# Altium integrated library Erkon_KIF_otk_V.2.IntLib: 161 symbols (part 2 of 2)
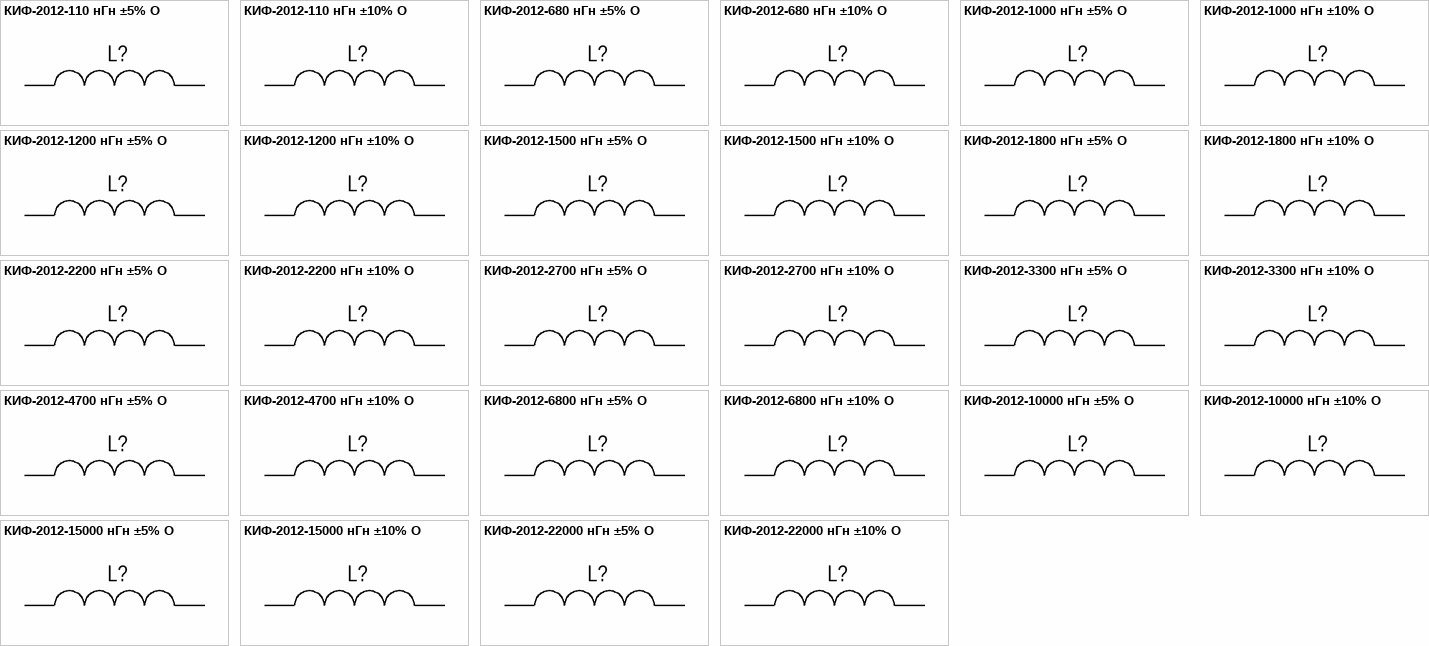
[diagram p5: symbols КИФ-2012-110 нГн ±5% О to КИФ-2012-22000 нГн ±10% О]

## КИФ-2012-1800 нГн ±5% О
designator L?, comment 1800 нГн ±5%  (value not drawn)
Катушка индуктивности с ферритовым сердечником; Добротность, не менее: 13; Резонансная частота, не менее: 0,3 ГГц; Сопротивление обмотки постоянноми току, не более: 1.2 Ом; Допустимый ток обмотки: 370 мА; Диапазон рабочих температур: от -60 до +125 ℃; Упаковка: Катушка и лента; Типоразмер: 2012 (0805); Технология монтажа: SMT; Изготовитель: АО "НПО "ЭРКОН"
footprint КИФ-2012-O (Катушка индуктивности с ферритовым сердечником типоразмер 2012(0805))
pins: 1, 2

## КИФ-2012-1800 нГн ±10% О
designator L?, comment 1800 нГн ±10%  (value not drawn)
Катушка индуктивности с ферритовым сердечником; Добротность, не менее: 13; Резонансная частота, не менее: 0.3 ГГц; Сопротивление обмотки постоянноми току, не более: 1.2 Ом; Допустимый ток обмотки: 370 мА; Диапазон рабочих температур: от -60 до +125 ℃; Упаковка: Катушка и лента; Типоразмер: 2012 (0805); Технология монтажа: SMT; Изготовитель: АО "НПО "ЭРКОН"
footprint КИФ-2012-O (Катушка индуктивности с ферритовым сердечником типоразмер 2012(0805))
pins: 1, 2

## КИФ-2012-2200 нГн ±5% О
designator L?, comment 2200 нГн ±5%  (value not drawn)
Катушка индуктивности с ферритовым сердечником; Добротность, не менее: 13; Резонансная частота, не менее: 0.105 ГГц; Сопротивление обмотки постоянноми току, не более: 1.47 Ом; Допустимый ток обмотки: 350 мА; Диапазон рабочих температур: от -60 до +125 ℃; Упаковка: Катушка и лента; Типоразмер: 2012 (0805); Технология монтажа: SMT; Изготовитель: АО "НПО "ЭРКОН"
footprint КИФ-2012-O (Катушка индуктивности с ферритовым сердечником типоразмер 2012(0805))
pins: 1, 2

## КИФ-2012-2200 нГн ±10% О
designator L?, comment 2200 нГн ±10%  (value not drawn)
Катушка индуктивности с ферритовым сердечником; Добротность, не менее: 13; Резонансная частота, не менее: 0.105 ГГц; Сопротивление обмотки постоянноми току, не более: 1.47 Ом; Допустимый ток обмотки: 350 мА; Диапазон рабочих температур: от -60 до +125 ℃; Упаковка: Катушка и лента; Типоразмер: 2012 (0805); Технология монтажа: SMT; Изготовитель: АО "НПО "ЭРКОН"
footprint КИФ-2012-O (Катушка индуктивности с ферритовым сердечником типоразмер 2012(0805))
pins: 1, 2

## КИФ-2012-2700 нГн ±5% О
designator L?, comment 2700 нГн ±5%  (value not drawn)
Катушка индуктивности с ферритовым сердечником; Добротность, не менее: 13; Резонансная частота, не менее: 0.10 ГГц; Сопротивление обмотки постоянноми току, не более: 1.7 Ом; Допустимый ток обмотки: 320 мА; Диапазон рабочих температур: от -60 до +125 ℃; Упаковка: Катушка и лента; Типоразмер: 2012 (0805); Технология монтажа: SMT; Изготовитель: АО "НПО "ЭРКОН"
footprint КИФ-2012-O (Катушка индуктивности с ферритовым сердечником типоразмер 2012(0805))
pins: 1, 2

## КИФ-2012-2700 нГн ±10% О
designator L?, comment 2700 нГн ±10%  (value not drawn)
Катушка индуктивности с ферритовым сердечником; Добротность, не менее: 13; Резонансная частота, не менее: 0.10 ГГц; Сопротивление обмотки постоянноми току, не более: 1.7 Ом; Допустимый ток обмотки: 320 мА; Диапазон рабочих температур: от -60 до +125 ℃; Упаковка: Катушка и лента; Типоразмер: 2012 (0805); Технология монтажа: SMT; Изготовитель: АО "НПО "ЭРКОН"
footprint КИФ-2012-O (Катушка индуктивности с ферритовым сердечником типоразмер 2012(0805))
pins: 1, 2

## КИФ-2012-3300 нГн ±5% О
designator L?, comment 3300 нГн ±5%  (value not drawn)
Катушка индуктивности с ферритовым сердечником; Добротность, не менее: 13; Резонансная частота, не менее: 0.085 ГГц; Сопротивление обмотки постоянноми току, не более: 1.8 Ом; Допустимый ток обмотки: 330 мА; Диапазон рабочих температур: от -60 до +125 ℃; Упаковка: Катушка и лента; Типоразмер: 2012 (0805); Технология монтажа: SMT; Изготовитель: АО "НПО "ЭРКОН"
footprint КИФ-2012-O (Катушка индуктивности с ферритовым сердечником типоразмер 2012(0805))
pins: 1, 2

## КИФ-2012-3300 нГн ±10% О
designator L?, comment 3300 нГн ±10%  (value not drawn)
Катушка индуктивности с ферритовым сердечником; Добротность, не менее: 13; Резонансная частота, не менее: 0.085 ГГц; Сопротивление обмотки постоянноми току, не более: 1.8 Ом; Допустимый ток обмотки: 330 мА; Диапазон рабочих температур: от -60 до +125 ℃; Упаковка: Катушка и лента; Типоразмер: 2012 (0805); Технология монтажа: SMT; Изготовитель: АО "НПО "ЭРКОН"
footprint КИФ-2012-O (Катушка индуктивности с ферритовым сердечником типоразмер 2012(0805))
pins: 1, 2

## КИФ-2012-4700 нГн ±5% О
designator L?, comment 4700 нГн ±5%  (value not drawn)
Катушка индуктивности с ферритовым сердечником; Добротность, не менее: 13; Резонансная частота, не менее: 0.055 ГГц; Сопротивление обмотки постоянноми току, не более: 2.2 Ом; Допустимый ток обмотки: 280 мА; Диапазон рабочих температур: от -60 до +125 ℃; Упаковка: Катушка и лента; Типоразмер: 2012 (0805); Технология монтажа: SMT; Изготовитель: АО "НПО "ЭРКОН"
footprint КИФ-2012-O (Катушка индуктивности с ферритовым сердечником типоразмер 2012(0805))
pins: 1, 2

## КИФ-2012-4700 нГн ±10% О
designator L?, comment 4700 нГн ±10%  (value not drawn)
Катушка индуктивности с ферритовым сердечником; Добротность, не менее: 13; Резонансная частота, не менее: 0.055 ГГц; Сопротивление обмотки постоянноми току, не более: 2.2 Ом; Допустимый ток обмотки: 280 мА; Диапазон рабочих температур: от -60 до +125 ℃; Упаковка: Катушка и лента; Типоразмер: 2012 (0805); Технология монтажа: SMT; Изготовитель: АО "НПО "ЭРКОН"
footprint КИФ-2012-O (Катушка индуктивности с ферритовым сердечником типоразмер 2012(0805))
pins: 1, 2

## КИФ-2012-6800 нГн ±5% О
designator L?, comment 6800 нГн ±5%  (value not drawn)
Катушка индуктивности с ферритовым сердечником; Добротность, не менее: 13; Резонансная частота, не менее: 0.035 ГГц; Сопротивление обмотки постоянноми току, не более: 2.8 Ом; Допустимый ток обмотки: 240 мА; Диапазон рабочих температур: от -60 до +125 ℃; Упаковка: Катушка и лента; Типоразмер: 2012 (0805); Технология монтажа: SMT; Изготовитель: АО "НПО "ЭРКОН"
footprint КИФ-2012-O (Катушка индуктивности с ферритовым сердечником типоразмер 2012(0805))
pins: 1, 2

## КИФ-2012-6800 нГн ±10% О
designator L?, comment 6800 нГн ±10%  (value not drawn)
Катушка индуктивности с ферритовым сердечником; Добротность, не менее: 13; Резонансная частота, не менее: 0.035 ГГц; Сопротивление обмотки постоянноми току, не более: 2.8 Ом; Допустимый ток обмотки: 240 мА; Диапазон рабочих температур: от -60 до +125 ℃; Упаковка: Катушка и лента; Типоразмер: 2012 (0805); Технология монтажа: SMT; Изготовитель: АО "НПО "ЭРКОН"
footprint КИФ-2012-O (Катушка индуктивности с ферритовым сердечником типоразмер 2012(0805))
pins: 1, 2

## КИФ-2012-10000 нГн ±5% О
designator L?, comment 10000 нГн ±5%  (value not drawn)
Катушка индуктивности с ферритовым сердечником; Добротность, не менее: 13; Резонансная частота, не менее: 0.019 ГГц; Сопротивление обмотки постоянноми току, не более: 3.3 Ом; Допустимый ток обмотки: 230 мА; Диапазон рабочих температур: от -60 до +125 ℃; Упаковка: Катушка и лента; Типоразмер: 2012 (0805); Технология монтажа: SMT; Изготовитель: АО "НПО "ЭРКОН"
footprint КИФ-2012-O (Катушка индуктивности с ферритовым сердечником типоразмер 2012(0805))
pins: 1, 2

## КИФ-2012-10000 нГн ±10% О
designator L?, comment 10000 нГн ±10%  (value not drawn)
Катушка индуктивности с ферритовым сердечником; Добротность, не менее: 13; Резонансная частота, не менее: 0.019 ГГц; Сопротивление обмотки постоянноми току, не более: 3.3 Ом; Допустимый ток обмотки: 230 мА; Диапазон рабочих температур: от -60 до +125 ℃; Упаковка: Катушка и лента; Типоразмер: 2012 (0805); Технология монтажа: SMT; Изготовитель: АО "НПО "ЭРКОН"
footprint КИФ-2012-O (Катушка индуктивности с ферритовым сердечником типоразмер 2012(0805))
pins: 1, 2

## КИФ-2012-15000 нГн ±5% О
designator L?, comment 15000 нГн ±5%  (value not drawn)
Катушка индуктивности с ферритовым сердечником; Добротность, не менее: 13; Резонансная частота, не менее: 0.015 ГГц; Сопротивление обмотки постоянноми току, не более: 6.3 Ом; Допустимый ток обмотки: 150 мА; Диапазон рабочих температур: от -60 до +125 ℃; Упаковка: Катушка и лента; Типоразмер: 2012 (0805); Технология монтажа: SMT; Изготовитель: АО "НПО "ЭРКОН"
footprint КИФ-2012-O (Катушка индуктивности с ферритовым сердечником типоразмер 2012(0805))
pins: 1, 2

## КИФ-2012-15000 нГн ±10% О
designator L?, comment 15000 нГн ±10%  (value not drawn)
Катушка индуктивности с ферритовым сердечником; Добротность, не менее: 13; Резонансная частота, не менее: 0.015 ГГц; Сопротивление обмотки постоянноми току, не более: 6.3 Ом; Допустимый ток обмотки: 150 мА; Диапазон рабочих температур: от -60 до +125 ℃; Упаковка: Катушка и лента; Типоразмер: 2012 (0805); Технология монтажа: SMT; Изготовитель: АО "НПО "ЭРКОН"
footprint КИФ-2012-O (Катушка индуктивности с ферритовым сердечником типоразмер 2012(0805))
pins: 1, 2

## КИФ-2012-22000 нГн ±5% О
designator L?, comment 22000 нГн ±5%  (value not drawn)
Катушка индуктивности с ферритовым сердечником; Добротность, не менее: 13; Резонансная частота, не менее: 0.01 ГГц; Сопротивление обмотки постоянноми току, не более: 10 Ом; Допустимый ток обмотки: 120 мА; Диапазон рабочих температур: от -60 до +125 ℃; Упаковка: Катушка и лента; Типоразмер: 2012 (0805); Технология монтажа: SMT; Изготовитель: АО "НПО "ЭРКОН"
footprint КИФ-2012-O (Катушка индуктивности с ферритовым сердечником типоразмер 2012(0805))
pins: 1, 2

## КИФ-2012-22000 нГн ±10% О
designator L?, comment 22000 нГн ±10%  (value not drawn)
Катушка индуктивности с ферритовым сердечником; Добротность, не менее: 13; Резонансная частота, не менее: 0.01 ГГц; Сопротивление обмотки постоянноми току, не более: 10 Ом; Допустимый ток обмотки: 120 мА; Диапазон рабочих температур: от -60 до +125 ℃; Упаковка: Катушка и лента; Типоразмер: 2012 (0805); Технология монтажа: SMT; Изготовитель: АО "НПО "ЭРКОН"
footprint КИФ-2012-O (Катушка индуктивности с ферритовым сердечником типоразмер 2012(0805))
pins: 1, 2


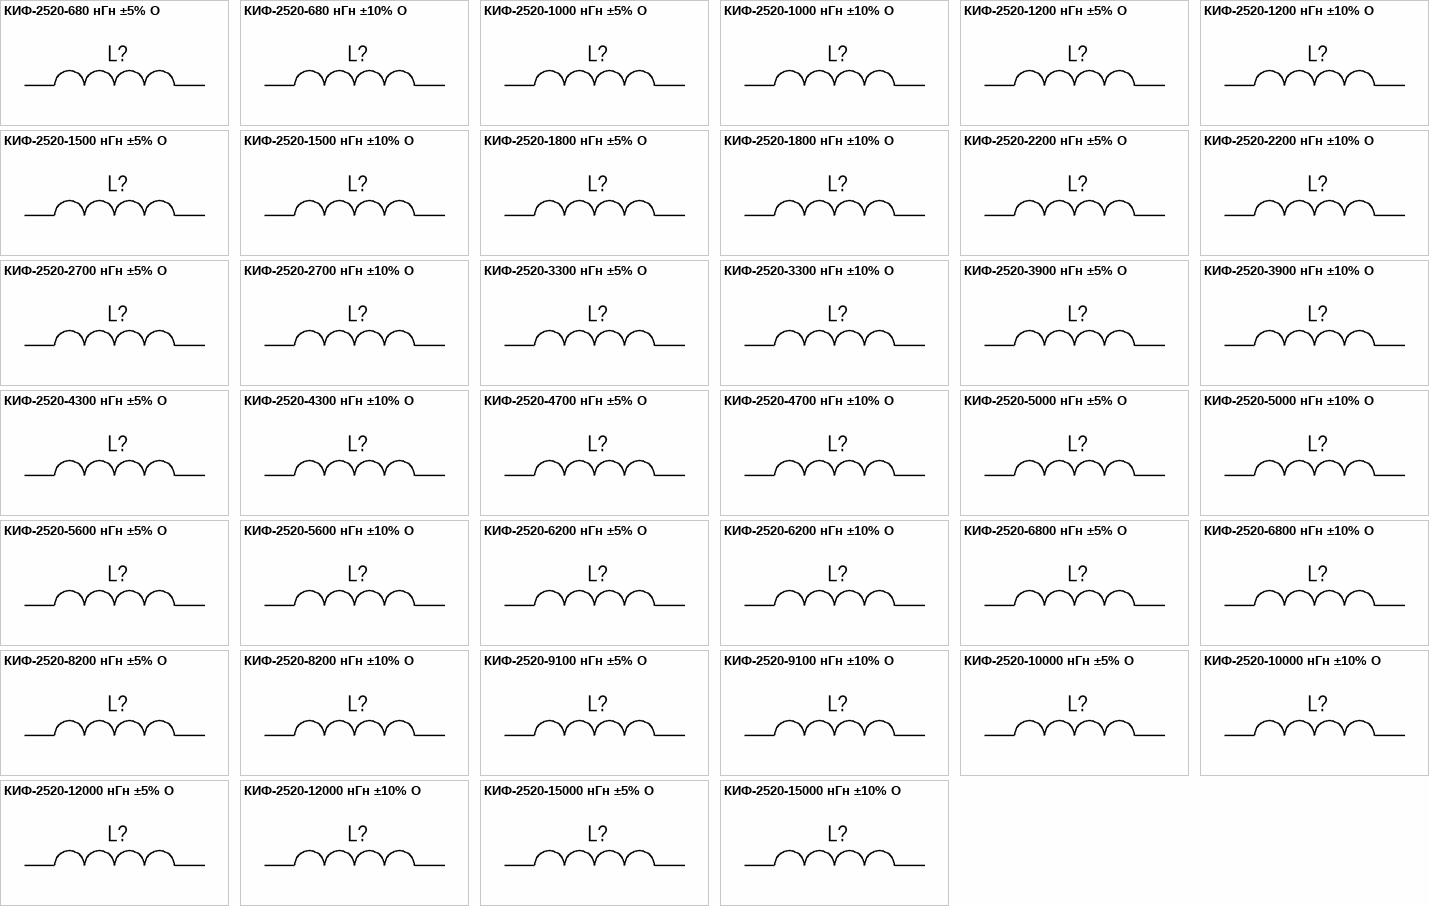
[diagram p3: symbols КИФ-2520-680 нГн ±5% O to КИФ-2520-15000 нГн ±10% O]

## КИФ-2520-680 нГн ±5% O
designator L?, comment 680 нГн ±5%  (value not drawn)
Катушка индуктивности с ферритовым сердечником; Номиналиная индуктивность: 680 нГн; Добротность, не менее: 50; Резонансная частота, не менее: 0.36 ГГц; Сопротивление обмотки постоянноми току, не более: 0.33 Ом; Допустимый ток обмотки: 600 мА; Упаковка: Катушка и лента; Типоразмер: 2520 (1008); Технология монтажа: SMT; Изготовитель: АО "НПО "ЭРКОН"
footprint КИФ-2520-O (Катушка индуктивности с ферритовым сердечником типоразмер 2520(1008))
pins: 1, 2

## КИФ-2520-680 нГн ±10% O
designator L?, comment 680 нГн ±10%  (value not drawn)
Катушка индуктивности с ферритовым сердечником; Номиналиная индуктивность: 680 нГн; Добротность, не менее: 50; Резонансная частота, не менее: 0.36 ГГц; Сопротивление обмотки постоянноми току, не более: 0.33 Ом; Допустимый ток обмотки: 600 мА; Упаковка: Катушка и лента; Типоразмер: 2520 (1008); Технология монтажа: SMT; Изготовитель: АО "НПО "ЭРКОН"
footprint КИФ-2520-O (Катушка индуктивности с ферритовым сердечником типоразмер 2520(1008))
pins: 1, 2

## КИФ-2520-1000 нГн ±5% O
designator L?, comment 1000 нГн ±5%  (value not drawn)
Катушка индуктивности с ферритовым сердечником; Добротность, не менее: 45; Резонансная частота, не менее: 0.33 ГГц; Сопротивление обмотки постоянноми току, не более: 0.4 Ом; Допустимый ток обмотки: 500 мА; Упаковка: Катушка и лента; Типоразмер: 2520 (1008); Технология монтажа: SMT; Изготовитель: АО "НПО "ЭРКОН"
footprint КИФ-2520-O (Катушка индуктивности с ферритовым сердечником типоразмер 2520(1008))
pins: 1, 2

## КИФ-2520-1000 нГн ±10% O
designator L?, comment 1000 нГн ±10%  (value not drawn)
Катушка индуктивности с ферритовым сердечником; Добротность, не менее: 45; Резонансная частота, не менее: 0.33 ГГц; Сопротивление обмотки постоянноми току, не более: 0.4 Ом; Допустимый ток обмотки: 500 мА; Упаковка: Катушка и лента; Типоразмер: 2520 (1008); Технология монтажа: SMT; Изготовитель: АО "НПО "ЭРКОН"
footprint КИФ-2520-O (Катушка индуктивности с ферритовым сердечником типоразмер 2520(1008))
pins: 1, 2

## КИФ-2520-1200 нГн ±5% O
designator L?, comment 1200 нГн ±5%  (value not drawn)
Катушка индуктивности с ферритовым сердечником; Добротность, не менее: 45; Резонансная частота, не менее: 0.3 ГГц; Сопротивление обмотки постоянноми току, не более: 0.6 Ом; Допустимый ток обмотки: 380 мА; Упаковка: Катушка и лента; Типоразмер: 2520 (1008); Технология монтажа: SMT; Изготовитель: АО "НПО "ЭРКОН"
footprint КИФ-2520-O (Катушка индуктивности с ферритовым сердечником типоразмер 2520(1008))
pins: 1, 2

## КИФ-2520-1200 нГн ±10% O
designator L?, comment 1200 нГн ±10%  (value not drawn)
Катушка индуктивности с ферритовым сердечником; Добротность, не менее: 45; Резонансная частота, не менее: 0.3 ГГц; Сопротивление обмотки постоянноми току, не более: 0.6 Ом; Допустимый ток обмотки: 380 мА; Упаковка: Катушка и лента; Типоразмер: 2520 (1008); Технология монтажа: SMT; Изготовитель: АО "НПО "ЭРКОН"
footprint КИФ-2520-O (Катушка индуктивности с ферритовым сердечником типоразмер 2520(1008))
pins: 1, 2

## КИФ-2520-1500 нГн ±5% O
designator L?, comment 1500 нГн ±5%  (value not drawn)
Катушка индуктивности с ферритовым сердечником; Добротность, не менее: 45; Резонансная частота, не менее: 0.25 ГГц; Сопротивление обмотки постоянноми току, не более: 0.65 Ом; Допустимый ток обмотки: 370 мА; Диапазон рабочих температур: от -60 до +125 ℃; Упаковка: Катушка и лента; Типоразмер: 2520 (1008); Технология монтажа: SMT; Изготовитель: АО "НПО "ЭРКОН"
footprint КИФ-2520-O (Катушка индуктивности с ферритовым сердечником типоразмер 2520(1008))
pins: 1, 2

## КИФ-2520-1500 нГн ±10% O
designator L?, comment 1500 нГн ±10%  (value not drawn)
Катушка индуктивности с ферритовым сердечником; Добротность, не менее: 45; Резонансная частота, не менее: 0.25 ГГц; Сопротивление обмотки постоянноми току, не более: 0.65 Ом; Допустимый ток обмотки: 370 мА; Упаковка: Катушка и лента; Типоразмер: 2520 (1008); Технология монтажа: SMT; Изготовитель: АО "НПО "ЭРКОН"
footprint КИФ-2520-O (Катушка индуктивности с ферритовым сердечником типоразмер 2520(1008))
pins: 1, 2

## КИФ-2520-1800 нГн ±5% O
designator L?, comment 1800 нГн ±5%  (value not drawn)
Катушка индуктивности с ферритовым сердечником; Добротность, не менее: 42; Резонансная частота, не менее: 0.23 ГГц; Сопротивление обмотки постоянноми току, не более: 0.84 Ом; Допустимый ток обмотки: 370 мА; Упаковка: Катушка и лента; Типоразмер: 2520 (1008); Технология монтажа: SMT; Изготовитель: АО "НПО "ЭРКОН"
footprint КИФ-2520-O (Катушка индуктивности с ферритовым сердечником типоразмер 2520(1008))
pins: 1, 2

## КИФ-2520-1800 нГн ±10% O
designator L?, comment 1800 нГн ±10%  (value not drawn)
Катушка индуктивности с ферритовым сердечником; Добротность, не менее: 42; Резонансная частота, не менее: 0.23 ГГц; Сопротивление обмотки постоянноми току, не более: 0.84 Ом; Допустимый ток обмотки: 370 мА; Упаковка: Катушка и лента; Типоразмер: 2520 (1008); Технология монтажа: SMT; Изготовитель: АО "НПО "ЭРКОН"
footprint КИФ-2520-O (Катушка индуктивности с ферритовым сердечником типоразмер 2520(1008))
pins: 1, 2

## КИФ-2520-2200 нГн ±5% O
designator L?, comment 2200 нГн ±5%  (value not drawn)
Катушка индуктивности с ферритовым сердечником; Добротность, не менее: 45; Резонансная частота, не менее: 0.17 ГГц; Сопротивление обмотки постоянноми току, не более: 1.1 Ом; Допустимый ток обмотки: 290 мА; Упаковка: Катушка и лента; Типоразмер: 2520 (1008); Технология монтажа: SMT; Изготовитель: АО "НПО "ЭРКОН"
footprint КИФ-2520-O (Катушка индуктивности с ферритовым сердечником типоразмер 2520(1008))
pins: 1, 2

## КИФ-2520-2200 нГн ±10% O
designator L?, comment 2200 нГн ±10%  (value not drawn)
Катушка индуктивности с ферритовым сердечником; Добротность, не менее: 45; Резонансная частота, не менее: 0.17 ГГц; Сопротивление обмотки постоянноми току, не более: 1.1 Ом; Допустимый ток обмотки: 290 мА; Упаковка: Катушка и лента; Типоразмер: 2520 (1008); Технология монтажа: SMT; Изготовитель: АО "НПО "ЭРКОН"
footprint КИФ-2520-O (Катушка индуктивности с ферритовым сердечником типоразмер 2520(1008))
pins: 1, 2

## КИФ-2520-2700 нГн ±5% O
designator L?, comment 2700 нГн ±5%  (value not drawn)
Катушка индуктивности с ферритовым сердечником; Добротность, не менее: 42; Резонансная частота, не менее: 0.135 ГГц; Сопротивление обмотки постоянноми току, не более: 1.28 Ом; Допустимый ток обмотки: 270 мА; Упаковка: Катушка и лента; Типоразмер: 2520 (1008); Технология монтажа: SMT; Изготовитель: АО "НПО "ЭРКОН"
footprint КИФ-2520-O (Катушка индуктивности с ферритовым сердечником типоразмер 2520(1008))
pins: 1, 2

## КИФ-2520-2700 нГн ±10% O
designator L?, comment 2700 нГн ±10%  (value not drawn)
Катушка индуктивности с ферритовым сердечником; Допускаемое отклонение индуктивности: ±5%; Добротность, не менее: 42; Резонансная частота, не менее: 0.135 ГГц; Сопротивление обмотки постоянноми току, не более: 1.28 Ом; Допустимый ток обмотки: 270 мА; Упаковка: Катушка и лента; Типоразмер: 2520 (1008); Технология монтажа: SMT; Изготовитель: АО "НПО "ЭРКОН"
footprint КИФ-2520-O (Катушка индуктивности с ферритовым сердечником типоразмер 2520(1008))
pins: 1, 2

## КИФ-2520-3300 нГн ±5% O
designator L?, comment 3300 нГн ±5%  (value not drawn)
Катушка индуктивности с ферритовым сердечником; Добротность, не менее: 37; Резонансная частота, не менее: 0.12 ГГц; Сопротивление обмотки постоянноми току, не более: 1.46 Ом; Допустимый ток обмотки: 260 мА; Упаковка: Катушка и лента; Типоразмер: 2520 (1008); Технология монтажа: SMT; Изготовитель: АО "НПО "ЭРКОН"
footprint КИФ-2520-O (Катушка индуктивности с ферритовым сердечником типоразмер 2520(1008))
pins: 1, 2

## КИФ-2520-3300 нГн ±10% O
designator L?, comment 3300 нГн ±10%  (value not drawn)
Катушка индуктивности с ферритовым сердечником; Добротность, не менее: 37; Резонансная частота, не менее: 0.12 ГГц; Сопротивление обмотки постоянноми току, не более: 1.46 Ом; Допустимый ток обмотки: 260 мА; Упаковка: Катушка и лента; Типоразмер: 2520 (1008); Технология монтажа: SMT; Изготовитель: АО "НПО "ЭРКОН"
footprint КИФ-2520-O (Катушка индуктивности с ферритовым сердечником типоразмер 2520(1008))
pins: 1, 2

## КИФ-2520-3900 нГн ±5% O
designator L?, comment 3900 нГн ±5%  (value not drawn)
Катушка индуктивности с ферритовым сердечником; Добротность, не менее: 32; Резонансная частота, не менее: 0.1 ГГц; Сопротивление обмотки постоянноми току, не более: 1.56 Ом; Допустимый ток обмотки: 250 мА; Упаковка: Катушка и лента; Типоразмер: 2520 (1008); Технология монтажа: SMT; Изготовитель: АО "НПО "ЭРКОН"
footprint КИФ-2520-O (Катушка индуктивности с ферритовым сердечником типоразмер 2520(1008))
pins: 1, 2

## КИФ-2520-3900 нГн ±10% O
designator L?, comment 3900 нГн ±10%  (value not drawn)
Катушка индуктивности с ферритовым сердечником; Добротность, не менее: 32; Резонансная частота, не менее: 0.1 ГГц; Сопротивление обмотки постоянноми току, не более: 1.56 Ом; Допустимый ток обмотки: 250 мА; Упаковка: Катушка и лента; Типоразмер: 2520 (1008); Технология монтажа: SMT; Изготовитель: АО "НПО "ЭРКОН"
footprint КИФ-2520-O (Катушка индуктивности с ферритовым сердечником типоразмер 2520(1008))
pins: 1, 2

## КИФ-2520-4300 нГн ±5% O
designator L?, comment 4300 нГн ±5%  (value not drawn)
Катушка индуктивности с ферритовым сердечником; Добротность, не менее: 30; Резонансная частота, не менее: 0.085 ГГц; Сопротивление обмотки постоянноми току, не более: 1.7 Ом; Допустимый ток обмотки: 230 мА; Упаковка: Катушка и лента; Типоразмер: 2520 (1008); Технология монтажа: SMT; Изготовитель: АО "НПО "ЭРКОН"
footprint КИФ-2520-O (Катушка индуктивности с ферритовым сердечником типоразмер 2520(1008))
pins: 1, 2

## КИФ-2520-4300 нГн ±10% O
designator L?, comment 4300 нГн ±10%  (value not drawn)
Катушка индуктивности с ферритовым сердечником; Добротность, не менее: 30; Резонансная частота, не менее: 0.085 ГГц; Сопротивление обмотки постоянноми току, не более: 1.7 Ом; Допустимый ток обмотки: 230 мА; Упаковка: Катушка и лента; Типоразмер: 2520 (1008); Технология монтажа: SMT; Изготовитель: АО "НПО "ЭРКОН"
footprint КИФ-2520-O (Катушка индуктивности с ферритовым сердечником типоразмер 2520(1008))
pins: 1, 2

## КИФ-2520-4700 нГн ±5% O
designator L?, comment 4700 нГн ±5%  (value not drawn)
Катушка индуктивности с ферритовым сердечником; Добротность, не менее: 32; Резонансная частота, не менее: 0.09 ГГц; Сопротивление обмотки постоянноми току, не более: 1.68 Ом; Допустимый ток обмотки: 230 мА; Упаковка: Катушка и лента; Типоразмер: 2520 (1008); Технология монтажа: SMT; Изготовитель: АО "НПО "ЭРКОН"
footprint КИФ-2520-O (Катушка индуктивности с ферритовым сердечником типоразмер 2520(1008))
pins: 1, 2

## КИФ-2520-4700 нГн ±10% O
designator L?, comment 4700 нГн ±10%  (value not drawn)
Катушка индуктивности с ферритовым сердечником; Добротность, не менее: 32; Резонансная частота, не менее: 0.09 ГГц; Сопротивление обмотки постоянноми току, не более: 1.68 Ом; Допустимый ток обмотки: 230 мА; Упаковка: Катушка и лента; Типоразмер: 2520 (1008); Технология монтажа: SMT; Изготовитель: АО "НПО "ЭРКОН"
footprint КИФ-2520-O (Катушка индуктивности с ферритовым сердечником типоразмер 2520(1008))
pins: 1, 2

## КИФ-2520-5000 нГн ±5% O
designator L?, comment 5000 нГн ±5%  (value not drawn)
Катушка индуктивности с ферритовым сердечником; Добротность, не менее: 28; Резонансная частота, не менее: 0.085 ГГц; Сопротивление обмотки постоянноми току, не более: 1.7 Ом; Допустимый ток обмотки: 200 мА; Упаковка: Катушка и лента; Типоразмер: 2520 (1008); Технология монтажа: SMT; Изготовитель: АО "НПО "ЭРКОН"
footprint КИФ-2520-O (Катушка индуктивности с ферритовым сердечником типоразмер 2520(1008))
pins: 1, 2

## КИФ-2520-5000 нГн ±10% O
designator L?, comment 5000 нГн ±10%  (value not drawn)
Катушка индуктивности с ферритовым сердечником; Добротность, не менее: 28; Резонансная частота, не менее: 0.085 ГГц; Сопротивление обмотки постоянноми току, не более: 1.7 Ом; Допустимый ток обмотки: 200 мА; Упаковка: Катушка и лента; Типоразмер: 2520 (1008); Технология монтажа: SMT; Изготовитель: АО "НПО "ЭРКОН"
footprint КИФ-2520-O (Катушка индуктивности с ферритовым сердечником типоразмер 2520(1008))
pins: 1, 2

## КИФ-2520-5600 нГн ±5% O
designator L?, comment 5600 нГн ±5%  (value not drawn)
Катушка индуктивности с ферритовым сердечником; Добротность, не менее: 25; Резонансная частота, не менее: 0.08 ГГц; Сопротивление обмотки постоянноми току, не более: 1.8 Ом; Допустимый ток обмотки: 200 мА; Упаковка: Катушка и лента; Типоразмер: 2520 (1008); Технология монтажа: SMT; Изготовитель: АО "НПО "ЭРКОН"
footprint КИФ-2520-O (Катушка индуктивности с ферритовым сердечником типоразмер 2520(1008))
pins: 1, 2

## КИФ-2520-5600 нГн ±10% O
designator L?, comment 5600 нГн ±10%  (value not drawn)
Катушка индуктивности с ферритовым сердечником; Добротность, не менее: 25; Резонансная частота, не менее: 0.08 ГГц; Сопротивление обмотки постоянноми току, не более: 1.8 Ом; Допустимый ток обмотки: 200 мА; Упаковка: Катушка и лента; Типоразмер: 2520 (1008); Технология монтажа: SMT; Изготовитель: АО "НПО "ЭРКОН"
footprint КИФ-2520-O (Катушка индуктивности с ферритовым сердечником типоразмер 2520(1008))
pins: 1, 2

## КИФ-2520-6200 нГн ±5% O
designator L?, comment 6200 нГн ±5%  (value not drawn)
Катушка индуктивности с ферритовым сердечником; Добротность, не менее: 28; Резонансная частота, не менее: 0.075 ГГц; Сопротивление обмотки постоянноми току, не более: 2 Ом; Допустимый ток обмотки: 200 мА; Упаковка: Катушка и лента; Типоразмер: 2520 (1008); Технология монтажа: SMT; Изготовитель: АО "НПО "ЭРКОН"
footprint КИФ-2520-O (Катушка индуктивности с ферритовым сердечником типоразмер 2520(1008))
pins: 1, 2

## КИФ-2520-6200 нГн ±10% O
designator L?, comment 6200 нГн ±10%  (value not drawn)
Катушка индуктивности с ферритовым сердечником; Добротность, не менее: 28; Резонансная частота, не менее: 0.075 ГГц; Сопротивление обмотки постоянноми току, не более: 2 Ом; Допустимый ток обмотки: 200 мА; Упаковка: Катушка и лента; Типоразмер: 2520 (1008); Технология монтажа: SMT; Изготовитель: АО "НПО "ЭРКОН"
footprint КИФ-2520-O (Катушка индуктивности с ферритовым сердечником типоразмер 2520(1008))
pins: 1, 2

## КИФ-2520-6800 нГн ±5% O
designator L?, comment 6800 нГн ±5%  (value not drawn)
Катушка индуктивности с ферритовым сердечником; Добротность, не менее: 28; Резонансная частота, не менее: 0.07 ГГц; Сопротивление обмотки постоянноми току, не более: 2.1 Ом; Допустимый ток обмотки: 200 мА; Упаковка: Катушка и лента; Типоразмер: 2520 (1008); Технология монтажа: SMT; Изготовитель: АО "НПО "ЭРКОН"
footprint КИФ-2520-O (Катушка индуктивности с ферритовым сердечником типоразмер 2520(1008))
pins: 1, 2

## КИФ-2520-6800 нГн ±10% O
designator L?, comment 6800 нГн ±10%  (value not drawn)
Катушка индуктивности с ферритовым сердечником; Добротность, не менее: 28; Резонансная частота, не менее: 0.07 ГГц; Сопротивление обмотки постоянноми току, не более: 2.1 Ом; Допустимый ток обмотки: 200 мА; Упаковка: Катушка и лента; Типоразмер: 2520 (1008); Технология монтажа: SMT; Изготовитель: АО "НПО "ЭРКОН"
footprint КИФ-2520-O (Катушка индуктивности с ферритовым сердечником типоразмер 2520(1008))
pins: 1, 2

## КИФ-2520-8200 нГн ±5% O
designator L?, comment 8200 нГн ±5%  (value not drawn)
Катушка индуктивности с ферритовым сердечником; Добротность, не менее: 20; Резонансная частота, не менее: 0.065 ГГц; Сопротивление обмотки постоянноми току, не более: 2.2 Ом; Допустимый ток обмотки: 190 мА; Упаковка: Катушка и лента; Типоразмер: 2520 (1008); Технология монтажа: SMT; Изготовитель: АО "НПО "ЭРКОН"
footprint КИФ-2520-O (Катушка индуктивности с ферритовым сердечником типоразмер 2520(1008))
pins: 1, 2

## КИФ-2520-8200 нГн ±10% O
designator L?, comment 8200 нГн ±10%  (value not drawn)
Катушка индуктивности с ферритовым сердечником; Добротность, не менее: 20; Резонансная частота, не менее: 0.065 ГГц; Сопротивление обмотки постоянноми току, не более: 2.2 Ом; Допустимый ток обмотки: 190 мА; Упаковка: Катушка и лента; Типоразмер: 2520 (1008); Технология монтажа: SMT; Изготовитель: АО "НПО "ЭРКОН"
footprint КИФ-2520-O (Катушка индуктивности с ферритовым сердечником типоразмер 2520(1008))
pins: 1, 2

## КИФ-2520-9100 нГн ±5% O
designator L?, comment 9100 нГн ±5%  (value not drawn)
Катушка индуктивности с ферритовым сердечником; Добротность, не менее: 26; Резонансная частота, не менее: 0.057 ГГц; Сопротивление обмотки постоянноми току, не более: 2.5 Ом; Допустимый ток обмотки: 170 мА; Упаковка: Катушка и лента; Типоразмер: 2520 (1008); Технология монтажа: SMT; Изготовитель: АО "НПО "ЭРКОН"
footprint КИФ-2520-O (Катушка индуктивности с ферритовым сердечником типоразмер 2520(1008))
pins: 1, 2

## КИФ-2520-9100 нГн ±10% O
designator L?, comment 9100 нГн ±10%  (value not drawn)
Катушка индуктивности с ферритовым сердечником; Добротность, не менее: 26; Резонансная частота, не менее: 0.057 ГГц; Сопротивление обмотки постоянноми току, не более: 2.5 Ом; Допустимый ток обмотки: 170 мА; Упаковка: Катушка и лента; Типоразмер: 2520 (1008); Технология монтажа: SMT; Изготовитель: АО "НПО "ЭРКОН"
footprint КИФ-2520-O (Катушка индуктивности с ферритовым сердечником типоразмер 2520(1008))
pins: 1, 2

## КИФ-2520-10000 нГн ±5% O
designator L?, comment 10000 нГн ±5%  (value not drawn)
Катушка индуктивности с ферритовым сердечником; Добротность, не менее: 24; Резонансная частота, не менее: 0.04 ГГц; Сопротивление обмотки постоянноми току, не более: 2.8 Ом; Допустимый ток обмотки: 165 мА; Упаковка: Катушка и лента; Типоразмер: 2520 (1008); Технология монтажа: SMT; Изготовитель: АО "НПО "ЭРКОН"
footprint КИФ-2520-O (Катушка индуктивности с ферритовым сердечником типоразмер 2520(1008))
pins: 1, 2

## КИФ-2520-10000 нГн ±10% O
designator L?, comment 10000 нГн ±10%  (value not drawn)
Катушка индуктивности с ферритовым сердечником; Добротность, не менее: 24; Резонансная частота, не менее: 0.04 ГГц; Сопротивление обмотки постоянноми току, не более: 2.8 Ом; Допустимый ток обмотки: 165 мА; Упаковка: Катушка и лента; Типоразмер: 2520 (1008); Технология монтажа: SMT; Изготовитель: АО "НПО "ЭРКОН"
footprint КИФ-2520-O (Катушка индуктивности с ферритовым сердечником типоразмер 2520(1008))
pins: 1, 2

## КИФ-2520-12000 нГн ±5% O
designator L?, comment 12000 нГн ±5%  (value not drawn)
Катушка индуктивности с ферритовым сердечником; Добротность, не менее: 28; Резонансная частота, не менее: 0.038 ГГц; Сопротивление обмотки постоянноми току, не более: 3.3 Ом; Допустимый ток обмотки: 160 мА; Упаковка: Катушка и лента; Типоразмер: 2520 (1008); Технология монтажа: SMT; Изготовитель: АО "НПО "ЭРКОН"
footprint КИФ-2520-O (Катушка индуктивности с ферритовым сердечником типоразмер 2520(1008))
pins: 1, 2

## КИФ-2520-12000 нГн ±10% O
designator L?, comment 12000 нГн ±10%  (value not drawn)
Катушка индуктивности с ферритовым сердечником; Добротность, не менее: 28; Резонансная частота, не менее: 0.038 ГГц; Сопротивление обмотки постоянноми току, не более: 3.3 Ом; Допустимый ток обмотки: 160 мА; Упаковка: Катушка и лента; Типоразмер: 2520 (1008); Технология монтажа: SMT; Изготовитель: АО "НПО "ЭРКОН"
footprint КИФ-2520-O (Катушка индуктивности с ферритовым сердечником типоразмер 2520(1008))
pins: 1, 2

## КИФ-2520-15000 нГн ±5% O
designator L?, comment 15000 нГн ±5%  (value not drawn)
Катушка индуктивности с ферритовым сердечником; Добротность, не менее: 28; Резонансная частота, не менее: 0.03 ГГц; Сопротивление обмотки постоянноми току, не более: 3.7 Ом; Допустимый ток обмотки: 150 мА; Упаковка: Катушка и лента; Типоразмер: 2520 (1008); Технология монтажа: SMT; Изготовитель: АО "НПО "ЭРКОН"
footprint КИФ-2520-O (Катушка индуктивности с ферритовым сердечником типоразмер 2520(1008))
pins: 1, 2

## КИФ-2520-15000 нГн ±10% O
designator L?, comment 15000 нГн ±10%  (value not drawn)
Катушка индуктивности с ферритовым сердечником; Добротность, не менее: 28; Резонансная частота, не менее: 0.03 ГГц; Сопротивление обмотки постоянноми току, не более: 3.7 Ом; Допустимый ток обмотки: 150 мА; Упаковка: Катушка и лента; Типоразмер: 2520 (1008); Технология монтажа: SMT; Изготовитель: АО "НПО "ЭРКОН"
footprint КИФ-2520-O (Катушка индуктивности с ферритовым сердечником типоразмер 2520(1008))
pins: 1, 2

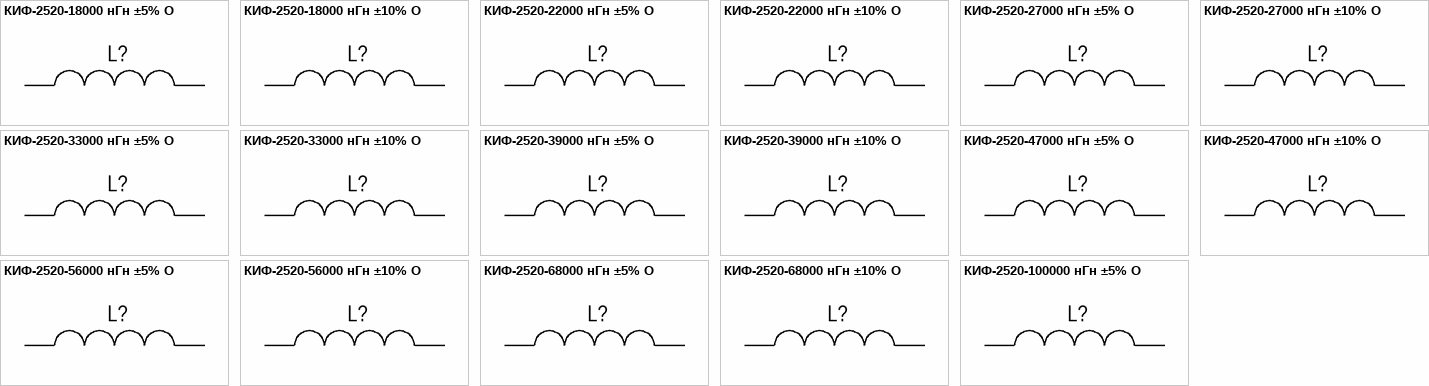
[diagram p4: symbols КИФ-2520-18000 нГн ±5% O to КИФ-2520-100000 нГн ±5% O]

## КИФ-2520-18000 нГн ±5% O
designator L?, comment 18000 нГн ±5%  (value not drawn)
Катушка индуктивности с ферритовым сердечником; Добротность, не менее: 28; Резонансная частота, не менее: 0.026 ГГц; Сопротивление обмотки постоянноми току, не более: 4 Ом; Допустимый ток обмотки: 140 мА; Упаковка: Катушка и лента; Типоразмер: 2520 (1008); Технология монтажа: SMT; Изготовитель: АО "НПО "ЭРКОН"
footprint КИФ-2520-O (Катушка индуктивности с ферритовым сердечником типоразмер 2520(1008))
pins: 1, 2

## КИФ-2520-18000 нГн ±10% O
designator L?, comment 18000 нГн ±10%  (value not drawn)
Катушка индуктивности с ферритовым сердечником; Добротность, не менее: 28; Резонансная частота, не менее: 0.026 ГГц; Сопротивление обмотки постоянноми току, не более: 4 Ом; Допустимый ток обмотки: 140 мА; Упаковка: Катушка и лента; Типоразмер: 2520 (1008); Технология монтажа: SMT; Изготовитель: АО "НПО "ЭРКОН"
footprint КИФ-2520-O (Катушка индуктивности с ферритовым сердечником типоразмер 2520(1008))
pins: 1, 2

## КИФ-2520-22000 нГн ±5% O
designator L?, comment 22000 нГн ±5%  (value not drawn)
Катушка индуктивности с ферритовым сердечником; Добротность, не менее: 28; Резонансная частота, не менее: 0.025 ГГц; Сопротивление обмотки постоянноми току, не более: 4.5 Ом; Допустимый ток обмотки: 115 мА; Упаковка: Катушка и лента; Типоразмер: 2520 (1008); Технология монтажа: SMT; Изготовитель: АО "НПО "ЭРКОН"
footprint КИФ-2520-O (Катушка индуктивности с ферритовым сердечником типоразмер 2520(1008))
pins: 1, 2

## КИФ-2520-22000 нГн ±10% O
designator L?, comment 22000 нГн ±10%  (value not drawn)
Катушка индуктивности с ферритовым сердечником; Добротность, не менее: 28; Резонансная частота, не менее: 0.025 ГГц; Сопротивление обмотки постоянноми току, не более: 4.5 Ом; Допустимый ток обмотки: 115 мА; Упаковка: Катушка и лента; Типоразмер: 2520 (1008); Технология монтажа: SMT; Изготовитель: АО "НПО "ЭРКОН"
footprint КИФ-2520-O (Катушка индуктивности с ферритовым сердечником типоразмер 2520(1008))
pins: 1, 2

## КИФ-2520-27000 нГн ±5% O
designator L?, comment 27000 нГн ±5%  (value not drawn)
Катушка индуктивности с ферритовым сердечником; Добротность, не менее: 28; Резонансная частота, не менее: 0.02 ГГц; Сопротивление обмотки постоянноми току, не более: 5.5 Ом; Допустимый ток обмотки: 110 мА; Упаковка: Катушка и лента; Типоразмер: 2520 (1008); Технология монтажа: SMT; Изготовитель: АО "НПО "ЭРКОН"
footprint КИФ-2520-O (Катушка индуктивности с ферритовым сердечником типоразмер 2520(1008))
pins: 1, 2

## КИФ-2520-27000 нГн ±10% O
designator L?, comment 27000 нГн ±10%  (value not drawn)
Катушка индуктивности с ферритовым сердечником; Добротность, не менее: 28; Резонансная частота, не менее: 0.02 ГГц; Сопротивление обмотки постоянноми току, не более: 5.5 Ом; Допустимый ток обмотки: 110 мА; Упаковка: Катушка и лента; Типоразмер: 2520 (1008); Технология монтажа: SMT; Изготовитель: АО "НПО "ЭРКОН"
footprint КИФ-2520-O (Катушка индуктивности с ферритовым сердечником типоразмер 2520(1008))
pins: 1, 2

## КИФ-2520-33000 нГн ±5% O
designator L?, comment 33000 нГн ±5%  (value not drawn)
Катушка индуктивности с ферритовым сердечником; Добротность, не менее: 28; Резонансная частота, не менее: 0.019 ГГц; Сопротивление обмотки постоянноми току, не более: 7 Ом; Допустимый ток обмотки: 110 мА; Упаковка: Катушка и лента; Типоразмер: 2520 (1008); Технология монтажа: SMT; Изготовитель: АО "НПО "ЭРКОН"
footprint КИФ-2520-O (Катушка индуктивности с ферритовым сердечником типоразмер 2520(1008))
pins: 1, 2

## КИФ-2520-33000 нГн ±10% O
designator L?, comment 33000 нГн ±10%  (value not drawn)
Катушка индуктивности с ферритовым сердечником; Добротность, не менее: 28; Резонансная частота, не менее: 0.019 ГГц; Сопротивление обмотки постоянноми току, не более: 7 Ом; Допустимый ток обмотки: 110 мА; Упаковка: Катушка и лента; Типоразмер: 2520 (1008); Технология монтажа: SMT; Изготовитель: АО "НПО "ЭРКОН"
footprint КИФ-2520-O (Катушка индуктивности с ферритовым сердечником типоразмер 2520(1008))
pins: 1, 2

## КИФ-2520-39000 нГн ±5% O
designator L?, comment 39000 нГн ±5%  (value not drawn)
Катушка индуктивности с ферритовым сердечником; Добротность, не менее: 32; Резонансная частота, не менее: 0.018 ГГц; Сопротивление обмотки постоянноми току, не более: 10 Ом; Допустимый ток обмотки: 90 мА; Упаковка: Катушка и лента; Типоразмер: 2520 (1008); Технология монтажа: SMT; Изготовитель: АО "НПО "ЭРКОН"
footprint КИФ-2520-O (Катушка индуктивности с ферритовым сердечником типоразмер 2520(1008))
pins: 1, 2

## КИФ-2520-39000 нГн ±10% O
designator L?, comment 39000 нГн ±10%  (value not drawn)
Катушка индуктивности с ферритовым сердечником; Добротность, не менее: 32; Резонансная частота, не менее: 0.018 ГГц; Сопротивление обмотки постоянноми току, не более: 10 Ом; Допустимый ток обмотки: 90 мА; Упаковка: Катушка и лента; Типоразмер: 2520 (1008); Технология монтажа: SMT; Изготовитель: АО "НПО "ЭРКОН"
footprint КИФ-2520-O (Катушка индуктивности с ферритовым сердечником типоразмер 2520(1008))
pins: 1, 2

## КИФ-2520-47000 нГн ±5% O
designator L?, comment 47000 нГн ±5%  (value not drawn)
Катушка индуктивности с ферритовым сердечником; Добротность, не менее: 30; Резонансная частота, не менее: 0.012 ГГц; Сопротивление обмотки постоянноми току, не более: 10.7 Ом; Допустимый ток обмотки: 80 мА; Упаковка: Катушка и лента; Типоразмер: 2520 (1008); Технология монтажа: SMT; Изготовитель: АО "НПО "ЭРКОН"
footprint КИФ-2520-O (Катушка индуктивности с ферритовым сердечником типоразмер 2520(1008))
pins: 1, 2

## КИФ-2520-47000 нГн ±10% O
designator L?, comment 47000 нГн ±10%  (value not drawn)
Катушка индуктивности с ферритовым сердечником; Добротность, не менее: 30; Резонансная частота, не менее: 0.012 ГГц; Сопротивление обмотки постоянноми току, не более: 10.7 Ом; Допустимый ток обмотки: 80 мА; Упаковка: Катушка и лента; Типоразмер: 2520 (1008); Технология монтажа: SMT; Изготовитель: АО "НПО "ЭРКОН"
footprint КИФ-2520-O (Катушка индуктивности с ферритовым сердечником типоразмер 2520(1008))
pins: 1, 2

## КИФ-2520-56000 нГн ±5% O
designator L?, comment 56000 нГн ±5%  (value not drawn)
Катушка индуктивности с ферритовым сердечником; Добротность, не менее: 16; Резонансная частота, не менее: 0.01 ГГц; Сопротивление обмотки постоянноми току, не более: 14.5 Ом; Допустимый ток обмотки: 70 мА; Упаковка: Катушка и лента; Типоразмер: 2520 (1008); Технология монтажа: SMT; Изготовитель: АО "НПО "ЭРКОН"
footprint КИФ-2520-O (Катушка индуктивности с ферритовым сердечником типоразмер 2520(1008))
pins: 1, 2

## КИФ-2520-56000 нГн ±10% O
designator L?, comment 56000 нГн ±10%  (value not drawn)
Катушка индуктивности с ферритовым сердечником; Добротность, не менее: 16; Резонансная частота, не менее: 0.01 ГГц; Сопротивление обмотки постоянноми току, не более: 14.5 Ом; Допустимый ток обмотки: 70 мА; Упаковка: Катушка и лента; Типоразмер: 2520 (1008); Технология монтажа: SMT; Изготовитель: АО "НПО "ЭРКОН"
footprint КИФ-2520-O (Катушка индуктивности с ферритовым сердечником типоразмер 2520(1008))
pins: 1, 2

## КИФ-2520-68000 нГн ±5% O
designator L?, comment 68000 нГн ±5%  (value not drawn)
Катушка индуктивности с ферритовым сердечником; Добротность, не менее: 14; Резонансная частота, не менее: 0.008 ГГц; Сопротивление обмотки постоянноми току, не более: 16.5 Ом; Допустимый ток обмотки: 75 мА; Упаковка: Катушка и лента; Типоразмер: 2520 (1008); Технология монтажа: SMT; Изготовитель: АО "НПО "ЭРКОН"
footprint КИФ-2520-O (Катушка индуктивности с ферритовым сердечником типоразмер 2520(1008))
pins: 1, 2

## КИФ-2520-68000 нГн ±10% O
designator L?, comment 68000 нГн ±10%  (value not drawn)
Катушка индуктивности с ферритовым сердечником; Добротность, не менее: 14; Резонансная частота, не менее: 0.008 ГГц; Сопротивление обмотки постоянноми току, не более: 16.5 Ом; Допустимый ток обмотки: 75 мА; Упаковка: Катушка и лента; Типоразмер: 2520 (1008); Технология монтажа: SMT; Изготовитель: АО "НПО "ЭРКОН"
footprint КИФ-2520-O (Катушка индуктивности с ферритовым сердечником типоразмер 2520(1008))
pins: 1, 2

## КИФ-2520-100000 нГн ±5% O
designator L?, comment 100000 нГн ±5%  (value not drawn)
Катушка индуктивности с ферритовым сердечником; Добротность, не менее: 14; Резонансная частота, не менее: 0.006 ГГц; Сопротивление обмотки постоянноми току, не более: 20.5 Ом; Допустимый ток обмотки: 65 мА; Упаковка: Катушка и лента; Типоразмер: 2520 (1008); Технология монтажа: SMT; Изготовитель: АО "НПО "ЭРКОН"
footprint КИФ-2520-O (Катушка индуктивности с ферритовым сердечником типоразмер 2520(1008))
pins: 1, 2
